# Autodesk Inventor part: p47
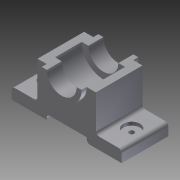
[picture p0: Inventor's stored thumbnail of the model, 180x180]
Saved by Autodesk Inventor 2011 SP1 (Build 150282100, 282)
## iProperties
Created: 2014-01
Part Number: p47
Document SubType Name: Modeling
Designer: Administrator
Density: 1 g/cm^3
Author: Administrator
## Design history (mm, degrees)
sketch "草图1"
  geometry: L1 (-33, 14)-(33, 14); L2 (33, 14)-(33, -14); L3 (33, -14)-(-33, -14); L4 (-33, -14)-(-33, 14); 3 further points
  constraints: 8 end point, 2 midpoint, 2 parallel, 1 horizontal, 1 horizontal alignment, 1 perpendicular, 1 vertical alignment
  dimensions: "d0" = 66 distance of L1.start L1.end; "d1" = 28 distance of L3.end L1.start
extrude "拉伸1" new body sketch "草图1" distance "d2" = 7; taper "d3" = 0 deg
sketch "草图2"
  geometry: L1 (-17.5, 14)-(17.5, 14); L2 (17.5, 14)-(17.5, -14); L3 (17.5, -14)-(-17.5, -14); L4 (-17.5, -14)-(-17.5, 14); 3 further points
  constraints: 8 end point, 2 midpoint, 2 parallel, 1 horizontal, 1 horizontal alignment, 1 perpendicular, 1 vertical alignment
  dimensions: "d4" = 35 distance of L1.start L1.end; "d5" = 28 distance of L1.end L2.end
extrude "拉伸2" join sketch "草图2" distance "d6" = 22; taper "d7" = 0 deg
hole "Hole1" diameter "d10" = 3; stored, may be unused: countersink angle "d14" = 90 deg, drill point angle "d16" = 0 deg; dims "d8" = 14, "d9" = 8, "d11" = 6, "d12" = 10, "d13" = 2, "d15" = 8
mirror "镜像1"
node "工作平面1"
sketch "草图3"
  geometry: L1 (-33, 0)-(33, 0) reference; L2 (-17.5, 29)-(17.5, 29) reference; A1 r 12 centre (0, 29) between (-12, 29) and (12, 29); 1 further point
  constraints: 2 point on circle, 2 point on line, 1 centre point, 1 midpoint
  dimensions: "d18" = 24 diameter of A1
extrude "拉伸3" join sketch "草图3" stored distance "d19" = 22; taper "d20" = 0 deg
mirror "镜像2"
sketch "草图4"
  geometry: L1 (12, 29)-(-12, 29) reference; L2 (-9, 29)-(9, 29); A1 r 12 centre (0, 29) between (-12, 29) and (12, 29) reference; A2 r 9 centre (0, 29) between (-9, 29) and (9, 29); 1 further point
  constraints: 2 end point, 2 point on circle, 2 point on line, 1 centre point, 1 coincident
  dimensions: "d21" = 18 diameter of A2
extrude "拉伸4" cut sketch "草图4" stored distance "d22" = 22; taper "d23" = 0 deg
sketch "草图5"
  geometry: L1 (9, 29)-(12, 29) reference; L2 (-12, 29)-(-9, 29) reference; C1 r 13 at (0, 29); A1 r 9 centre (0, 29) between (-9, 29) and (9, 29) reference; 1 further point
  constraints: 1 centre point, 1 coincident
  dimensions: "d24" = 26 diameter of C1
extrude "拉伸5" cut sketch "草图5" stored distance "d25" = 16; taper "d26" = 0 deg
sketch "草图6"
  geometry: L1 (66, 0)-(0, 0) reference; L2 (21, 3)-(45, 3); L3 (45, 3)-(45, 0); L4 (45, 0)-(21, 0); L5 (21, 0)-(21, 3); 2 further points
  constraints: 8 end point, 2 midpoint, 2 parallel, 1 horizontal, 1 perpendicular
  dimensions: "d27" = 3 distance of L4.end L2.start; "d28" = 24 distance of L2.start L2.end
extrude "拉伸6" cut sketch "草图6" stored distance "d29" = 16; taper "d30" = 0 deg
fillet "圆角1" dims "d31" = 2
fillet "圆角2" dims "d32" = 2
fillet "圆角3" dims "d33" = 2
fillet "圆角4" dims "d34" = 2
fillet "圆角5" dims "d35" = 2
fillet "圆角6" dims "d36" = 2
node "实体1"
other parameters: "d17" = -17
